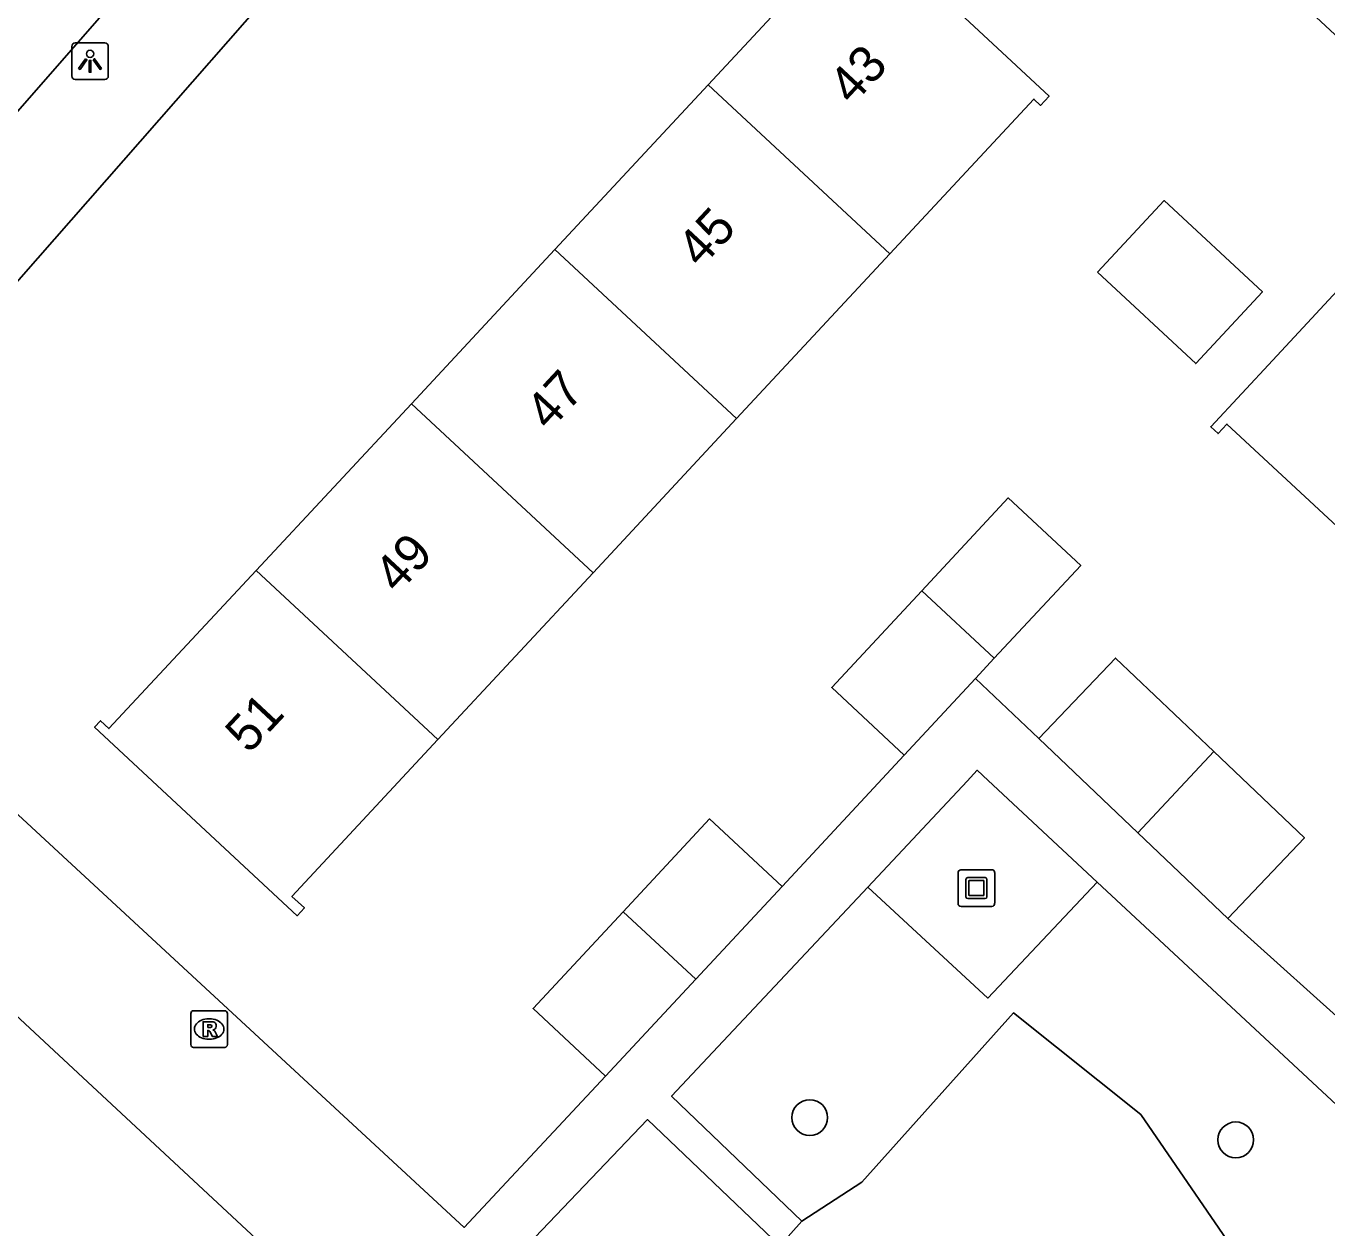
# Model space of a CAD drawing. Extents: x 159222 to 160346, y 381249 to 382166.
# Drawn here: x 159752.91 to 159788.43, y 381588.83 to 381621.64 of the extents above; entities that cross this region are included whole.
import ezdxf

# ---------------------------------------------------------------- set-up
doc = ezdxf.new("R2010")
doc.units = 0
for name, color, linetype in [('IMGEO_Boom', 7, 'Continuous'), ('IMGEO_Groenvoorziening', 7, 'Continuous'), ('IMGEO_Kunstobject', 7, 'Continuous'), ('IMGEO_Lichtpunt', 7, 'Continuous'), ('IMGEO_Pand', 7, 'Continuous'), ('IMGEO_Pand_nummerreeks', 7, 'Continuous'), ('IMGEO_Rijbaan_lokaal_open', 7, 'Continuous'), ('IMGEO_Rioolput', 7, 'Continuous'), ('IMGEO_Voetpad_open', 7, 'Continuous')]:
    doc.layers.add(name, color=color, linetype=linetype)

msp = doc.modelspace()

# ---------------------------------------------------------------- linework, layer by layer
at = {"layer": 'IMGEO_Boom'}
for centre in [(159774.306, 381591.842), (159785.935, 381591.235)]:
    msp.add_circle(centre, 0.489, dxfattribs=at)
at = {"layer": 'IMGEO_Groenvoorziening'}
for points in [[(159782.155, 381598.273), (159779.167, 381595.105), (159775.893, 381598.132)], [(159774.092, 381589.012), (159775.732, 381590.085), (159779.873, 381594.699), (159783.341, 381591.926), (159786.426, 381587.433), (159787.316, 381583.835), (159788.398, 381582.74)]]:
    msp.add_lwpolyline(points, dxfattribs=at)
at = {"layer": 'IMGEO_Kunstobject'}
for p, q in [((159778.355, 381598.524), (159778.355, 381597.683)), ((159778.355, 381598.524), (159778.355, 381597.683)), ((159779.271, 381598.608), (159778.43, 381598.608)), ((159779.271, 381598.608), (159778.43, 381598.608)), ((159779.355, 381597.692), (159779.355, 381598.533)), ((159779.355, 381597.692), (159779.355, 381598.533)), ((159778.569, 381597.872), (159778.569, 381598.346)), ((159778.619, 381598.396), (159779.093, 381598.396)), ((159778.649, 381598.296), (159778.649, 381597.922)), ((159779.043, 381598.316), (159778.669, 381598.316)), ((159779.063, 381597.922), (159779.063, 381598.296)), ((159779.143, 381598.346), (159779.143, 381597.872)), ((159779.093, 381597.822), (159778.619, 381597.822)), ((159778.669, 381597.902), (159779.043, 381597.902)), ((159778.439, 381597.608), (159779.28, 381597.608)), ((159778.439, 381597.608), (159779.28, 381597.608))]:
    msp.add_line(p, q, dxfattribs=at)
for centre, radius, start, end in [((159778.433, 381598.53), 0.0779, 92.4484, 184.2845), ((159778.433, 381598.53), 0.0779, 92.4484, 184.2845), ((159779.277, 381598.53), 0.0779, 2.4484, 94.2845), ((159779.277, 381598.53), 0.0779, 2.4484, 94.2845), ((159778.619, 381598.346), 0.05, 90, 180), ((159778.669, 381598.296), 0.02, 90, 180), ((159779.043, 381598.296), 0.02, 360, 90), ((159779.093, 381598.346), 0.05, 360, 90), ((159778.619, 381597.872), 0.05, 180, 270), ((159778.669, 381597.922), 0.02, 180, 270), ((159779.043, 381597.922), 0.02, 270, 0), ((159779.093, 381597.872), 0.05, 270, 0), ((159778.433, 381597.686), 0.0779, 182.4484, 274.2845), ((159778.433, 381597.686), 0.0779, 182.4484, 274.2845), ((159779.277, 381597.686), 0.0779, 272.4484, 4.2845), ((159779.277, 381597.686), 0.0779, 272.4484, 4.2845)]:
    msp.add_arc(centre, radius, start, end, dxfattribs=at)
at = {"layer": 'IMGEO_Lichtpunt'}
for p, q in [((159754.162, 381621.08), (159754.162, 381620.273)), ((159754.162, 381621.08), (159754.162, 381620.273)), ((159755.064, 381621.175), (159754.256, 381621.175)), ((159755.064, 381621.175), (159754.256, 381621.175)), ((159755.158, 381620.273), (159755.158, 381621.08)), ((159755.158, 381620.273), (159755.158, 381621.08)), ((159754.256, 381620.179), (159755.064, 381620.179)), ((159754.256, 381620.179), (159755.064, 381620.179))]:
    msp.add_line(p, q, dxfattribs=at)
for points in [[(159754.536, 381620.744), (159754.575, 381620.716), (159754.387, 381620.454), (159754.349, 381620.481), (159754.536, 381620.744)], [(159754.638, 381620.696), (159754.685, 381620.696), (159754.685, 381620.374), (159754.638, 381620.374), (159754.638, 381620.696)], [(159754.748, 381620.716), (159754.786, 381620.743), (159754.973, 381620.481), (159754.934, 381620.453), (159754.748, 381620.716)]]:
    msp.add_lwpolyline(points, dxfattribs=at)
msp.add_circle((159754.661, 381620.878), 0.0994, dxfattribs=at)
for centre, start, end in [((159754.256, 381621.08), 90, 180), ((159754.256, 381621.08), 90, 180), ((159755.064, 381621.08), 0, 90), ((159755.064, 381621.08), 0, 90), ((159754.256, 381620.273), 180, 270), ((159754.256, 381620.273), 180, 270), ((159755.064, 381620.273), 270, 0), ((159755.064, 381620.273), 270, 360)]:
    msp.add_arc(centre, 0.0946, start, end, dxfattribs=at)
at = {"layer": 'IMGEO_Pand'}
for points in [[(159771.532, 381620.03), (159775.476, 381624.268), (159775.245, 381624.483), (159775.467, 381624.722), (159780.842, 381619.72), (159780.61, 381619.471), (159780.425, 381619.642), (159776.491, 381615.416)], [(159767.352, 381615.54), (159771.532, 381620.03)], [(159771.532, 381620.03), (159776.491, 381615.416)], [(159782.165, 381614.916), (159783.982, 381616.871), (159786.662, 381614.38), (159784.846, 381612.425), (159782.165, 381614.916)], [(159789.957, 381606.81), (159785.693, 381610.772), (159785.453, 381610.514), (159785.255, 381610.698), (159786.948, 381612.519), (159790.351, 381616.181), (159790.548, 381615.997), (159790.268, 381615.695), (159794.532, 381611.733)], [(159763.433, 381611.329), (159767.352, 381615.54)], [(159772.311, 381610.925), (159767.352, 381615.54)], [(159776.491, 381615.416), (159772.311, 381610.925)], [(159759.198, 381606.78), (159763.433, 381611.329)], [(159763.433, 381611.329), (159768.393, 381606.714)], [(159772.311, 381610.925), (159768.393, 381606.714)], [(159777.366, 381606.22), (159779.726, 381608.756), (159781.704, 381606.915), (159779.344, 381604.38)], [(159764.158, 381602.164), (159760.172, 381597.882), (159760.513, 381597.564), (159760.315, 381597.352), (159754.784, 381602.5), (159754.947, 381602.675), (159755.178, 381602.46), (159759.198, 381606.78)], [(159764.158, 381602.164), (159759.198, 381606.78)], [(159768.393, 381606.714), (159764.158, 381602.164)], [(159777.366, 381606.22), (159774.908, 381603.578), (159776.885, 381601.739)], [(159779.344, 381604.38), (159777.366, 381606.22)], [(159778.832, 381603.83), (159779.344, 381604.38)], [(159785.334, 381601.835), (159782.652, 381604.385), (159780.56, 381602.186)], [(159778.832, 381603.83), (159776.885, 381601.739)], [(159783.267, 381599.611), (159780.56, 381602.186)], [(159785.334, 381601.835), (159783.267, 381599.611)], [(159785.719, 381597.279), (159787.811, 381599.479), (159785.334, 381601.835)], [(159769.217, 381597.463), (159771.573, 381599.995), (159773.551, 381598.154)], [(159785.719, 381597.279), (159783.267, 381599.611)], [(159773.551, 381598.154), (159771.194, 381595.623)], [(159768.732, 381592.978), (159766.755, 381594.817), (159769.217, 381597.463)], [(159771.194, 381595.623), (159769.217, 381597.463)], [(159771.194, 381595.623), (159768.732, 381592.978)]]:
    msp.add_lwpolyline(points, dxfattribs=at)
at = {"layer": 'IMGEO_Rijbaan_lokaal_open'}
msp.add_lwpolyline([(159755.864, 381622.952), (159752.56, 381619.17)], dxfattribs=at)
at = {"layer": 'IMGEO_Rioolput'}
for p, q in [((159757.411, 381593.834), (159757.411, 381594.686)), ((159757.486, 381594.76), (159758.338, 381594.76)), ((159758.412, 381594.686), (159758.412, 381593.834)), ((159757.899, 381594.54), (159757.924, 381594.54)), ((159757.922, 381593.98), (159757.897, 381593.98)), ((159758.338, 381593.76), (159757.486, 381593.76))]:
    msp.add_line(p, q, dxfattribs=at)
for points in [[(159757.411, 381593.834), (159757.411, 381594.686)], [(159757.486, 381594.76), (159758.338, 381594.76)], [(159758.412, 381594.686), (159758.412, 381593.834)], [(159758, 381594.458), (159757.748, 381594.46), (159757.748, 381594.06)], [(159757.926, 381594.379), (159757.872, 381594.379), (159757.872, 381594.298)], [(159757.872, 381594.298), (159757.924, 381594.298)], [(159757.748, 381594.06), (159757.872, 381594.06), (159757.872, 381594.222), (159757.883, 381594.222)], [(159757.93, 381594.193), (159758.001, 381594.06), (159758.141, 381594.06), (159758.076, 381594.186)], [(159758.338, 381593.76), (159757.486, 381593.76)]]:
    msp.add_lwpolyline(points, dxfattribs=at)
for centre, radius, start, end in [((159757.488, 381594.684), 0.0765, 91.552, 178.448), ((159757.488, 381594.684), 0.0765, 91.552, 178.448), ((159758.336, 381594.684), 0.0765, 1.552, 88.448), ((159758.336, 381594.684), 0.0765, 1.552, 88.448), ((159757.908, 381594.487), 0.19, 274.7715, 282.9687), ((159757.932, 381594.283), 0.0964, 77.0061, 93.1865), ((159757.946, 381594.34), 0.0378, 276.6634, 79.6772), ((159757.999, 381594.348), 0.109, 350.3612, 89.416), ((159757.997, 381594.348), 0.112, 277.5842, 350.9817), ((159757.882, 381594.169), 0.0533, 26.0293, 88.6989), ((159757.981, 381594.133), 0.108, 29.5134, 73.7905), ((159757.488, 381593.836), 0.0765, 181.552, 268.448), ((159757.488, 381593.836), 0.0765, 181.552, 268.448), ((159758.336, 381593.836), 0.0765, 271.552, 358.448), ((159758.336, 381593.836), 0.0765, 271.552, 358.448)]:
    msp.add_arc(centre, radius, start, end, dxfattribs=at)
for centre, major_axis, ratio, start_param, end_param in [((159757.898, 381594.26), (-0.387, 0.002), 0.722429, 4.712389, 7.853982), ((159757.923, 381594.26), (-0.39, 0.002), 0.717154, 1.570796, 4.712389)]:
    msp.add_ellipse(centre, major_axis=major_axis, ratio=ratio, start_param=start_param, end_param=end_param, dxfattribs=at)
at = {"layer": 'IMGEO_Voetpad_open'}
for points in [[(159770.255, 381634.704), (159770.41, 381634.827), (159770.644, 381634.984), (159770.891, 381635.12), (159771.149, 381635.234), (159771.416, 381635.323), (159771.689, 381635.389), (159771.968, 381635.43), (159772.249, 381635.446), (159772.531, 381635.436), (159772.811, 381635.402), (159773.086, 381635.343), (159773.355, 381635.259), (159773.615, 381635.152), (159773.865, 381635.022), (159774.102, 381634.87), (159774.325, 381634.697), (159814.342, 381597.549)], [(159745.629, 381606.638), (159770.255, 381634.704)], [(159768.732, 381592.978), (159764.873, 381588.845), (159745.629, 381606.638)], [(159743.027, 381603.569), (159787.302, 381562.373)], [(159780.56, 381602.186), (159778.832, 381603.83)], [(159776.885, 381601.739), (159773.551, 381598.154)], [(159775.893, 381598.132), (159778.606, 381601.023), (159778.879, 381601.324), (159779.175, 381601.048), (159782.155, 381598.273)], [(159782.155, 381598.273), (159793.91, 381587.329), (159789.727, 381582.805)], [(159774.092, 381589.012), (159770.536, 381592.424), (159775.893, 381598.132)], [(159789.405, 381593.965), (159785.719, 381597.279)], [(159771.559, 381582.662), (159766.038, 381587.767), (159769.874, 381591.787), (159773.488, 381588.347)], [(159773.488, 381588.347), (159774.092, 381589.012)]]:
    msp.add_lwpolyline(points, dxfattribs=at)

# ---------------------------------------------------------------- texts
at = {"layer": 'IMGEO_Pand_nummerreeks'}
for s, p in [('43', (159775.468, 381619.445)), ('45', (159771.331, 381615)), ('47', (159767.194, 381610.556)), ('49', (159763.058, 381606.112)), ('51', (159758.998, 381601.75))]:
    msp.add_text(s, height=1, rotation=47.0539, dxfattribs=at).set_placement(p)

doc.saveas('drawing.dxf')
